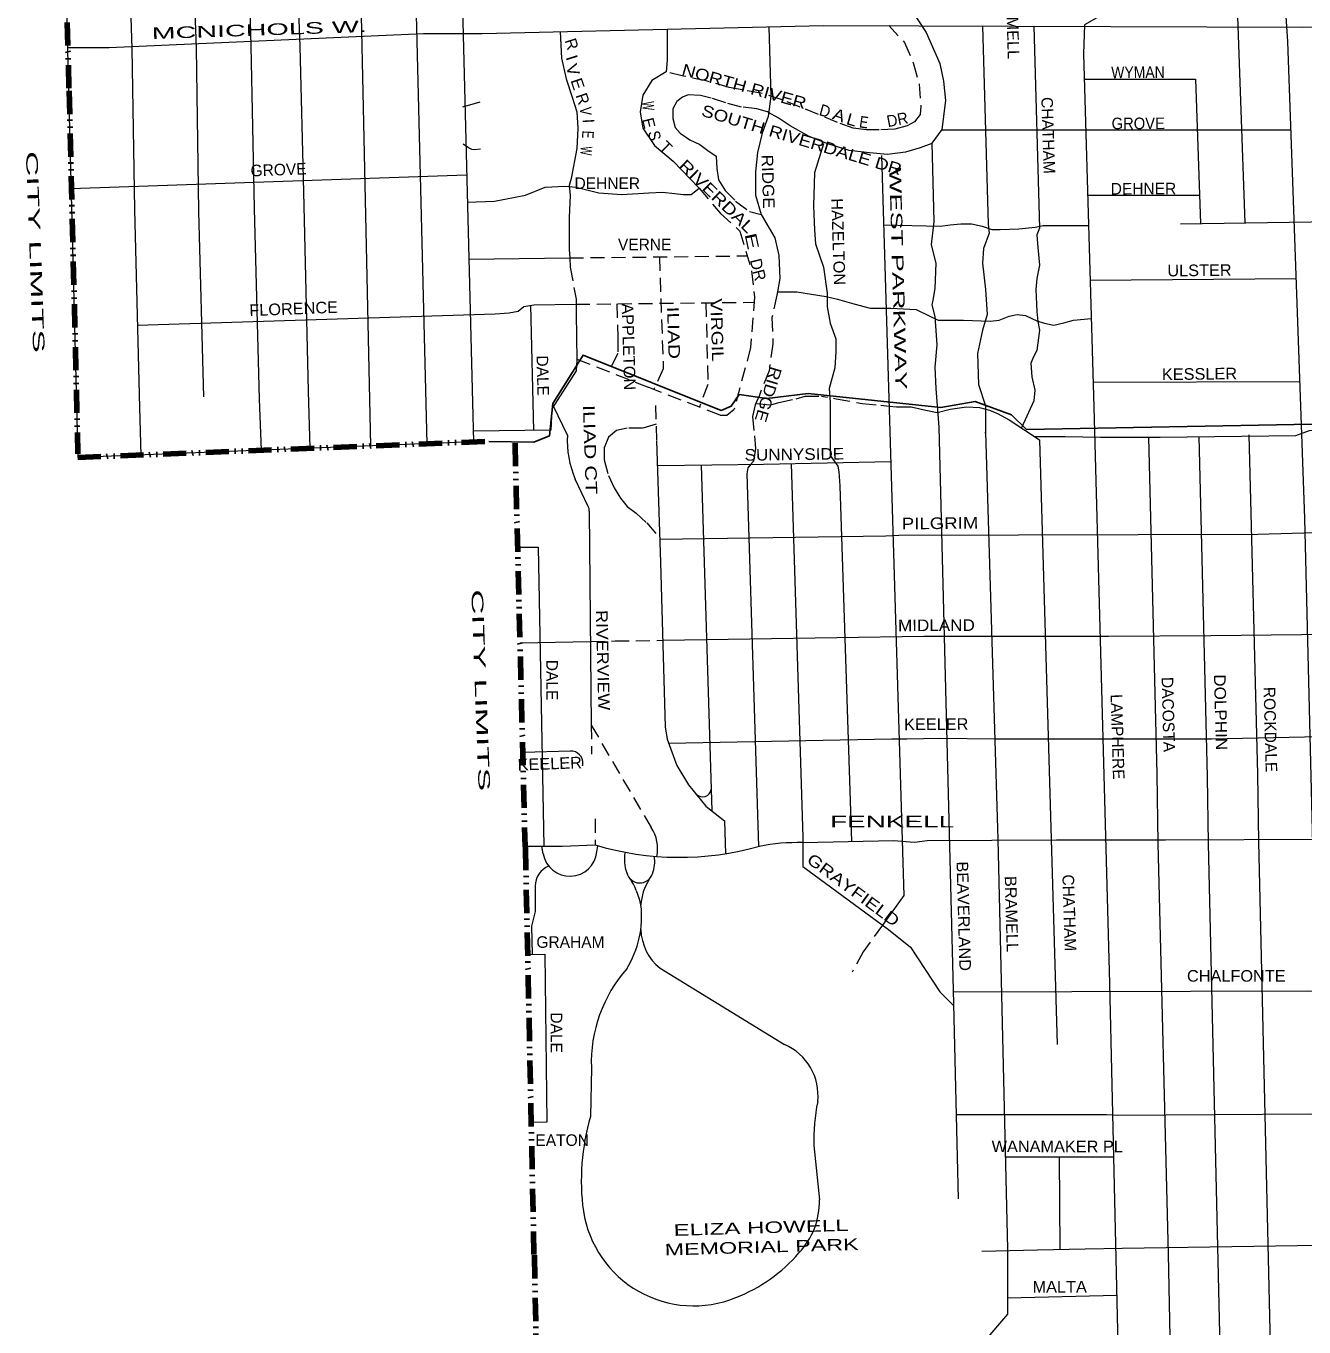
# Model space of a CAD drawing. Extents: x 34705 to 138605, y 34275 to 143551.
# Drawn here: x 34920 to 43181, y 121964 to 130370 of the extents above; entities that cross this region are included whole.
import ezdxf
from ezdxf.enums import TextEntityAlignment as Align

# ---------------------------------------------------------------- set-up
doc = ezdxf.new("R2010")
doc.units = 0
doc.header["$LTSCALE"] = 30
doc.linetypes.add('DASH_DOUBLE_DOT', pattern=[9.2, 5, -1.2, 0.3, -1.2, 0.3, -1.2])
doc.linetypes.add('MEDIUM_DASHED', pattern=[4.5, 3, -1.5])
for name, color, linetype, lineweight in [('1', 7, 'Continuous', 13), ('11', 7, 'Continuous', 13), ('59', 7, 'DASH_DOUBLE_DOT', 106)]:
    doc.layers.add(name, color=color, linetype=linetype, lineweight=lineweight)

msp = doc.modelspace()

# ---------------------------------------------------------------- linework, layer by layer
at = {"layer": '1'}
for p, q in [((34922.9, 140631.57), (35253.71, 127582.24)), ((41761.4, 130025.76), (42478.95, 130025.76)), ((42478.95, 130025.76), (42511.27, 129093.75)), ((37853.74, 129878.69), (37741.43, 129846.2)), ((40836.67, 129698.57), (43094.26, 129698.57)), ((35209.64, 129320.94), (37767.98, 129408.65)), ((41783.12, 129276.39), (42504.93, 129276.39)), ((42382.42, 129091.68), (46341.01, 129155.36)), ((37781.68, 128864.48), (38434.34, 128871.92)), ((41799.02, 128727.48), (43128.63, 128738.28)), ((38180.29, 128565.69), (38199.83, 127757.67)), ((41818.13, 128067.95), (43152.42, 128073.24)), ((38419.62, 127726.26), (38329.53, 127914.49)), ((37811.41, 127682.75), (35253.71, 127582.23)), ((38311.91, 127759.44), (37809.68, 127751.5)), ((39284.01, 127533.76), (39353.85, 125298.36)), ((38552.48, 127269.04), (38470.77, 127442.74)), ((38560.88, 127235.16), (38573.99, 125851.86)), ((38113.08, 126384.45), (38568.85, 126393.52)), ((38438.66, 125684.69), (38130.75, 125677.2)), ((38262.53, 125021.1), (38253.15, 125069.67)), ((38610.21, 125034.11), (38616.97, 125073.43)), ((38211.88, 124812.27), (38210.95, 124649.13)), ((38865.05, 124784.28), (38882.82, 124731.17)), ((38210.92, 124648.89), (38187.51, 124554.54)), ((38187.48, 124554.28), (38192.15, 124370.92)), ((39018.66, 124282.29), (39822.71, 123789.22)), ((38574.29, 123639.56), (38568.77, 123325.34)), ((40012.98, 123136.45), (40048.64, 122785.47)), ((41251.44, 123063.4), (41949.57, 123063.4)), ((41597.84, 123063.4), (41603.99, 122465.81)), ((41265.57, 122153.74), (41970.48, 122169.5))]:
    msp.add_line(p, q, dxfattribs=at)
at = {"layer": '1', "linetype": 'MEDIUM_DASHED'}
for p, q in [((38434.34, 128871.92), (39581.77, 128885.01)), ((38475.23, 128572.32), (39626.43, 128585.3)), ((38989.41, 127919.19), (38996.49, 127689.53)), ((38573.99, 125851.86), (38575.76, 125665.07)), ((38573.99, 125851.86), (38961.55, 125191.17)), ((38598.19, 125246.63), (38598.95, 125080.57))]:
    msp.add_line(p, q, dxfattribs=at)
at = {"layer": '1'}
for points in [[(42731.15, 140854.29), (42770.72, 138315.69), (42820.32, 138221.97), (42809.3, 138139.28), (42831.34, 137610.03), (42902.99, 132838.56), (43073.83, 130269.5), (43184.06, 127189.13), (43401.06, 118420.74)], [(37454.38, 140703.77), (37375.53, 140338.99), (37375.53, 140279.38), (37330.84, 140078.2), (37271.25, 139541.72), (37293.59, 139079.75), (37397.87, 138438.96), (37479.81, 138044.05), (37546.85, 137492.67), (37591.54, 136419.71), (37811.41, 127682.75)], [(36490.17, 135510.11), (36506.88, 134551.8), (36569.73, 134518.26), (36600.45, 133540.44), (36620.6, 132875.53), (36611.44, 132752.81), (36580.31, 132659.39), (36618.77, 131119.41), (36629.75, 130705.44), (36679.19, 130524.11), (36690.18, 130237.91), (36713.98, 129298.25), (36743.28, 128010.12), (36754.84, 127642.86)], [(37189.87, 135540.54), (37218.37, 134190.17), (37347.71, 134120.16), (37377.91, 132902.64), (37365.37, 132789.74), (37315.21, 132695.65), (37302.67, 132589.02), (37359.1, 130699.45), (37440.61, 130530.1), (37511.01, 127671.07)], [(35564.96, 135465.63), (35570.87, 135082.21), (35461.47, 135140.95), (35486.2, 134138.09), (35575.93, 131095.66), (35603.39, 130225.61), (35619.87, 129182.93), (35652.83, 127905.78), (35662.29, 127598.32)], [(35878.83, 135480.1), (35892.71, 135038.36), (35885.38, 134798.41), (35898.2, 134147.25), (35987.92, 131106.65), (36019.05, 130229.27), (36033.7, 129171.94), (36066.59, 127974.42)], [(36198.03, 135494.82), (36230.63, 134724.12), (36245.49, 134715.44), (36280.9, 133431.06), (36348.65, 131115.81), (36372.45, 130242.1), (36394.43, 129190.25), (36427.39, 127958.9), (36439, 127628.88)], [(42985.69, 131594.9), (42798.27, 131148.83), (42699.07, 130972.41), (42610.89, 130862.15), (41762.17, 130377.01), (41756.66, 130189.57), (41822.79, 127907.19), (41923.37, 124183.18), (42021.75, 119977.21)], [(35186.55, 130231.58), (35458.2, 130231.58), (37489.31, 130321.29), (37869.15, 130321.29), (40074.35, 130374.07), (43172.44, 130363.51), (44385.83, 130374.07), (48329.33, 130516.55), (49305.31, 130558.77), (49933.11, 130564.05), (54929.09, 130685.43), (56976.03, 130759.31), (58131.38, 130785.7), (58991.3, 130812.08), (60184.9, 130901.8), (61393.02, 130975.68), (61503.8, 130980.96), (63404.33, 131007.34), (65002.84, 131017.9), (66400.87, 131039.01), (66997.01, 131039.01), (67635.36, 131075.95), (68722.14, 131123.45), (70126.76, 131153.79)], [(36995.41, 131165.19), (37014.23, 130713.57), (37033.04, 130625.75), (37083.2, 130537.94), (37146.23, 127656.72)], [(42622.5, 130876.66), (42699.07, 130729.84), (42732.14, 130696.76), (42743.16, 130674.71), (42798.45, 129098.37)], [(40644.8, 130472.07), (40738.86, 130327.81), (40826.64, 130127.09), (40851.73, 130014.18), (40864.27, 129888.73), (40839.18, 129700.56), (40776.48, 129612.74), (40789.02, 129107.82), (40770.21, 128957.28), (40801.56, 128838.1), (40795.29, 128675.02), (40782.75, 128599.75), (40776.48, 128568.39), (40795.29, 128493.12), (40807.83, 128311.22), (40795.29, 128166.95), (40801.56, 128028.96), (40820.37, 127778.06), (40914.43, 124141.62), (40945.78, 122793.04)], [(38373.37, 130333.36), (38381.18, 130161.59), (38412.53, 130029.87), (38450.15, 129910.69), (38481.51, 129816.61), (38487.78, 129709.97), (38481.51, 129578.25), (38443.88, 129383.81), (38431.34, 129339.9), (38437.61, 129277.18), (38431.34, 129132.91), (38431.34, 128925.92), (38434.34, 128871.92)], [(39064.65, 130349.9), (39064.65, 130149.05), (39058.38, 130073.78), (38964.33, 130017.33), (38907.89, 129923.24), (38889.08, 129816.61), (38907.89, 129709.97), (38983.14, 129597.07), (39102.28, 129496.71), (39270.64, 129321.81)], [(39722, 130365.64), (39735.59, 129916.97), (39716.78, 129785.24), (39679.16, 129678.61), (39647.8, 129553.16), (39635.26, 129427.71), (39635.26, 129277.18), (39672.89, 129151.73), (39760.67, 129001.19), (39785.75, 128888.28), (39792.02, 128737.74), (39777.18, 128653.66)], [(41102.11, 130370.57), (41140.17, 129089), (41146.44, 129032.55), (41108.81, 128932.19), (41102.54, 128838.1), (41121.35, 128668.75), (41133.89, 128505.66), (41102.54, 128405.3), (41071.19, 128254.76), (41077.46, 128054.05), (41121.35, 127916.05), (41121.35, 127740.42), (41121.35, 127746.69), (41202.87, 125113.85), (41265.57, 122466.87), (41265.57, 122046.61), (40958.32, 121689.08)], [(41434.11, 130369.44), (41472.5, 129063.91), (41453.69, 129020), (41459.96, 128938.46), (41472.5, 128825.56), (41453.69, 128737.74), (41447.42, 128668.75), (41453.69, 128524.48), (41459.96, 128461.76), (41472.5, 128405.3), (41453.69, 128273.58), (41434.88, 128235.95), (41416.06, 128192.04), (41422.33, 128104.23), (41441.15, 128016.41), (41434.88, 127947.41), (41354.12, 127773.43)], [(40776.5, 129612.09), (40699.51, 129582.47), (40604.55, 129556.08), (40488.48, 129540.25), (40372.42, 129550.81), (40240.53, 129566.64), (40103.36, 129608.86), (39982.03, 129656.35), (39860.69, 129724.96), (39781.55, 129777.73), (39720.41, 129810.66)], [(37745.82, 129608.16), (37785.59, 129580.82), (37800.49, 129574.39), (37816.64, 129572.72), (37857.44, 129577.53)], [(40074.19, 129609.62), (40017.76, 129421.44), (40011.49, 129208.18), (40017.76, 129051.37), (40024.03, 128963.55), (40074.19, 128813.01), (40099.27, 128643.66), (40099.27, 128555.84), (40118.09, 128449.21), (40155.71, 128348.85), (40155.71, 128267.31), (40149.44, 128160.68), (40111.82, 128028.96), (40118.09, 127934.87), (40118.09, 127596.16), (40168.25, 127527.16), (40174.52, 127489.52), (40180.79, 127398.58), (40256.07, 125101.73)], [(40450.42, 129534.35), (40594.64, 124751.6), (40456.13, 124560.28)], [(37772.42, 129232.41), (37948.29, 129239.45), (38148.76, 129276.39), (38275.37, 129329.16), (38401.99, 129334.44), (38475.85, 129329.16), (38623.56, 129292.22), (38771.28, 129281.66), (38945.37, 129292.22), (39035.06, 129297.5), (39114.19, 129286.94), (39166.95, 129281.66), (39219.7, 129281.66), (39270.27, 129321.52)], [(40463.92, 129086.5), (40831.4, 129075.85), (40894.7, 129086.4), (40963.29, 129091.68), (41031.87, 129091.68), (41100.45, 129075.85), (41163.76, 129054.74), (41216.52, 129054.74), (41337.85, 129060.02), (41443.37, 129070.57), (41496.12, 129081.13), (41788.78, 129081.13)], [(39777.18, 128653.66), (39902.89, 128653.66), (40092.81, 128622), (40166.67, 128606.17), (40272.18, 128574.5), (40377.7, 128548.12), (40509.58, 128548.12), (40673.13, 128537.56), (40762.81, 128495.34), (40815.57, 128468.96), (40979.11, 128468.96), (41153.21, 128463.68), (41211.24, 128468.96), (41274.55, 128495.34), (41327.3, 128505.9), (41380.06, 128500.62), (41459.19, 128463.68), (41511.95, 128447.85), (41564.7, 128437.29), (41628.01, 128453.13), (41691.32, 128468.96), (41806.21, 128479.4)], [(35639.14, 128436.32), (37953.56, 128511.18), (38043.25, 128516.45), (38101.28, 128527.01), (38138.21, 128558.67), (38201.51, 128569.23), (38475.23, 128572.32)], [(38475.23, 128572.32), (38475.23, 128511.94), (38481.51, 128210.86), (38475.23, 128141.86), (38318.47, 127897.23), (38311.91, 127759.44)], [(40499.26, 127914.54), (40546.51, 127909.56), (40641.47, 127909.56), (40736.44, 127888.45), (40810.29, 127872.62), (40894.7, 127893.73), (41000.22, 127909.56), (41084.63, 127904.29), (41147.93, 127888.45), (41200.69, 127867.34), (41274.55, 127825.13), (41472.13, 127696.75)], [(41439.59, 127717.9), (41636.79, 127718.72), (41865.41, 127714.3), (42250.53, 127714.3), (43127.6, 127724.86), (43217.28, 127756.52), (48761.16, 127885.97)], [(38996.49, 127689.53), (39020.76, 126903.06), (39052.11, 125843.01), (39064.65, 125761.47), (39127.36, 125592.11), (39202.6, 125466.66), (39315.47, 125328.67), (39434.61, 125234.58), (39441.69, 125022.08)], [(41472.13, 127696.75), (41472.5, 127696.52), (41585.37, 123790.36)], [(42175.91, 127713.4), (42230.62, 125535.23), (42236.13, 125088.68), (42303.65, 122435.56), (42353.02, 119975.33)], [(42500.56, 127717.31), (42555.78, 125518.7), (42561.29, 125088.68), (42680.27, 119968.71)], [(42825.83, 127729.41), (42880.94, 125535.23), (42886.45, 125099.71), (42981.52, 121013.21)], [(39001.43, 127529.61), (39354.23, 127534.87), (39686.59, 127540.15), (40510.06, 127556.52)], [(39605.88, 127538.87), (39585.1, 127514.61), (39578.83, 127476.98), (39654.75, 125068.94)], [(39866.65, 127543.73), (39942.51, 125127.95), (39942.51, 125008.77), (39942.51, 124939.78), (40494.31, 124532.07), (40638.53, 124419.16), (40826.64, 124130.63), (40917.05, 124040.19)], [(39016.09, 127054.55), (40477.93, 127075.75), (40562.34, 127081.02), (42883.6, 127086.3), (44889.65, 127144.35), (45000.43, 127144.35), (46145.24, 127165.46), (49096.07, 127229.34)], [(38097.6, 127003.42), (38230.69, 127003.42), (38267.86, 125070.07)], [(39035.59, 126401.44), (40724.71, 126427.53), (41115.04, 126427.53), (41916.92, 126427.53), (42580.01, 126431.39), (43166, 126439.1), (44149.07, 126462.24), (50761.79, 126624.85)], [(39073.76, 125736.85), (40516.53, 125764.23), (40612.91, 125764.23), (40829.76, 125768.08), (41180.58, 125764.23), (41862.94, 125764.23), (42583.86, 125764.23), (43285.51, 125779.65), (44496.99, 125814.36), (45807.75, 125852.92), (46189.42, 125856.78), (48457.74, 125899.57)], [(39941.51, 125093.75), (40528.09, 125108.63), (40663.03, 125097.06), (40744.94, 125108.63), (41581.52, 125112.49), (42287.01, 125112.49), (43300.93, 125116.35), (44878.65, 125170.34), (48156.52, 125239.75), (49710.15, 125274.46), (51827.61, 125340.02), (53217.9, 125389.91), (53477.78, 125395.11), (53786.04, 125409.43)], [(38145.93, 125070.07), (38384.61, 125070.07), (38598.99, 125079.53)], [(40914.75, 124129.1), (43212.26, 124136.81), (43354.9, 124132.95), (44281.1, 124159.95), (49507.13, 124287.78), (49653.37, 124366.55), (49872.73, 124366.55), (53583.68, 124493.23)], [(38158.66, 124370.57), (38274.58, 124373.7), (38287.12, 123288.56), (38185.49, 123285.57)], [(40933.12, 123337.57), (41905.35, 123337.57), (41978.6, 123333.72), (43223.82, 123341.43), (43362.61, 123337.57), (44543.25, 123376.14), (44998.16, 123391.56), (45869.44, 123418.56), (45965.82, 123414.7), (48528.39, 123465.41)], [(41099.62, 122454.45), (41458.15, 122462.16), (41766.57, 122469.88), (42005.59, 122473.73), (43281.65, 122493.01), (43412.73, 122485.3), (47717.02, 122597.14), (53834.22, 122766.82), (57551.33, 122855.98)]]:
    msp.add_lwpolyline(points, dxfattribs=at)
at = {"layer": '1', "linetype": 'MEDIUM_DASHED'}
for points in [[(40497.21, 130372.63), (40599.27, 130263.24), (40657.3, 130126.03), (40694.23, 129994.1), (40704.78, 129851.61), (40699.51, 129798.84), (40662.58, 129751.34), (40615.1, 129724.96), (40535.96, 129703.85), (40435.73, 129698.57), (40351.32, 129698.57), (40266.91, 129709.13), (40166.67, 129746.07), (39923.99, 129846.34), (39807.93, 129893.83), (39670.76, 129936.05), (39549.43, 129957.16), (39465.02, 129972.99), (39317.3, 130015.21), (39169.58, 130046.87), (39058.38, 130073.78)], [(39720.41, 129810.66), (39712.97, 129814.67), (39644.39, 129835.78), (39544.15, 129846.34), (39443.91, 129872.72), (39348.95, 129904.39), (39280.37, 129920.22), (39201.24, 129925.5), (39164.31, 129909.66), (39127.38, 129883.28), (39101, 129835.78), (39101, 129772.45), (39116.83, 129714.4), (39148.48, 129677.46), (39211.79, 129635.24), (39275.09, 129603.58), (39327.85, 129566.64), (39380.61, 129529.7), (39385.88, 129450.54), (39396.43, 129376.65), (39438.64, 129308.05), (39507.22, 129239.44), (39596.91, 129170.84), (39672.81, 129151.86)], [(39270.27, 129321.52), (39409.53, 129158), (39534.94, 129045.09), (39610.18, 128787.92), (39628.99, 128618.57), (39603.91, 128292.4), (39497.65, 127895.57)], [(38434.34, 128871.92), (38437.61, 128813.01), (38475.23, 128606.02), (38475.23, 128572.32)], [(39013.94, 128878.53), (39039.57, 128154.4), (38977.28, 128022.86)], [(39777.18, 128653.66), (39773.21, 128631.11), (39741.86, 128486.85), (39748.13, 128317.49), (39723.05, 128141.86), (39660.35, 127985.05), (39633.65, 127922.81), (39616.45, 127847.05), (39628.99, 127721.61), (39635.26, 127640.06), (39622.72, 127558.52), (39605.88, 127538.87)], [(38738.38, 128575.29), (38744.86, 128355.12), (38744.86, 128254.76), (38686.25, 128137.49)], [(39315.3, 128581.79), (39328.01, 128054.05), (39272.66, 127908.7)], [(38481.35, 128218.4), (38942.73, 128036.22), (39406.98, 127856.79), (39449.19, 127856.79), (39497.65, 127895.57)], [(39639.14, 127932.01), (39735.68, 127922.81), (39786.69, 127936.73), (39897.62, 127962.34), (39955.65, 127978.17), (40061.16, 127978.17), (40100.32, 127971.64)], [(40139.38, 127965.13), (40156.12, 127962.34), (40324.94, 127930.67), (40446.28, 127920.12), (40499.26, 127914.54)], [(38993.17, 127797.32), (38905.8, 127772.35), (38805.57, 127772.35), (38736.98, 127756.52), (38684.23, 127714.3), (38657.85, 127645.7), (38657.85, 127566.54), (38684.23, 127466.27), (38721.16, 127387.11), (38763.36, 127318.5), (38805.57, 127265.73), (38863.6, 127223.51), (38932.18, 127160.18), (39015.87, 127061.52)], [(38568.85, 126393.52), (38727.73, 126396.68), (39035.59, 126401.44)], [(40456.13, 124560.28), (40331.28, 124387.8), (40260.4, 124256.17)]]:
    msp.add_lwpolyline(points, dxfattribs=at)
at = {"layer": '1', "lineweight": 25}
msp.add_lwpolyline([(37911.41, 127686.12), (38203.24, 127680.58), (38303.04, 127721.95), (38325.81, 127931.49), (38521.05, 128243.98), (39412.67, 127885.92), (39479.2, 127912.86), (39529.81, 127990.08), (39707.77, 127962.88), (39975.21, 127996.38), (40834.68, 127905.45), (41055.96, 127944.51), (41290.17, 127858.28), (41387.87, 127762.23), (48773.97, 127901.51)], dxfattribs=at)
at = {"layer": '1'}
for centre, radius, start, end in [((39033, 127690.56), 614.42, 176.66935, 203.78642), ((38510.54, 127240.66), 50.63, 353.76439, 34.09313), ((38443.02, 125608.16), 76.66, 43.69087, 93.26007), ((39293.14, 125447.17), 57.26, 224.34198, 350.14515), ((38762.66, 125056.32), 240.29, 347.60729, 34.13847), ((39146.1, 126895.46), 1896.56, 253.23335, 285.75016), ((39910.76, 123779.37), 1314.74, 88.65959, 101.07292), ((38435.54, 125052), 175.58, 189.99921, 354.15384), ((39042.87, 124986.91), 254.99, 169.7126, 200.16834), ((38781.3, 124970.3), 203.33, 337.75481, 9.84394), ((38346.03, 124815.82), 134.19, 110.89611, 181.51783), ((38887.31, 124919.67), 86.31, 193.8638, 342.22316), ((38645.97, 124729.85), 220.69, 29.15279, 38.63534), ((38706.01, 124738.44), 165.51, 16.07827, 36.70265), ((39214.27, 124678.5), 319.38, 146.49402, 177.70857), ((38252.97, 124618.26), 646.3, 328.32716, 6.48591), ((38724.07, 124660.29), 173.85, 10.26399, 24.06033), ((38209.95, 124649.13), 1, 346.06698, 359.67256), ((38188.48, 124554.3), 1, 166.06698, 181.45729), ((39226.07, 124541.32), 331.83, 181.58545, 231.31593), ((39496.32, 123670.29), 922.54, 138.72171, 181.90879), ((39683.65, 123461.21), 356.26, 353.4065, 67.0248), ((41218.62, 123175.07), 1206.26, 168.26958, 181.83431), ((39994.08, 122909.89), 1484.63, 163.74961, 187.65769), ((39570.43, 122774.1), 478.35, 316.3607, 1.36264), ((39235.84, 122822.95), 721.72, 188.83911, 292.11571), ((39139.66, 123108.17), 1022.15, 291.09202, 319.47412)]:
    msp.add_arc(centre, radius, start, end, dxfattribs=at)
at = {"layer": '1', "linetype": 'MEDIUM_DASHED'}
msp.add_arc((38443.02, 125608.16), 76.66, 346.35543, 43.69136, dxfattribs=at)
at = {"layer": '59'}
for p, q in [((35198.5, 129951.49), (35255.46, 127605.67)), ((35253.71, 127582.24), (37903.63, 127686.52)), ((38080.81, 127675.25), (38145.99, 125067.44)), ((38148.2, 125065.12), (38203.39, 122431.77)), ((38205.78, 122428.72), (38232.86, 121106.59))]:
    msp.add_line(p, q, dxfattribs=at)
msp.add_lwpolyline([(34926.08, 140631.66), (34977.99, 138118.71), (35197.94, 129943.33)], dxfattribs=at)

# ---------------------------------------------------------------- texts
at = {"layer": '1', "width": 2.25}
for p in [(34942.21, 128909.07), (37821.95, 126077.21)]:
    msp.add_text('CITY LIMITS', height=75, rotation=272.106, dxfattribs=at).set_placement(p, align=Align.CENTER)
at = {"layer": '11'}
for s, rotation, width, p in [('BRAMELL', 271.52, 1.05, (41259.96, 130401.08)), ('MCNICHOLS W.', 1.91, 1.85, (36428.75, 130308.39)), ('I', 287.519, 1.15, (38412.64, 130154)), ('V', 287.519, 1.1, (38418.61, 130076.15)), ('NORTH RIVER', 344.384, 1.2, (39552.68, 129944.21)), ('WYMAN', 0.421, 0.9, (42108.32, 130033.96)), ('E', 288.435, 1.1, (38450.48, 129984.25)), ('W', 272.201, 0.6, (38905.2, 129853.09)), ('V', 273.365, 0.8, (38500.21, 129818.39)), ('SOUTH RIVERDALE DR', 343.311, 1.2, (39923.69, 129598.64)), ('D', 344.384, 0.95, (40074.78, 129785.82)), ('A', 340.807, 1.15, (40163.54, 129758.26)), ('L', 344.384, 1.15, (40247.94, 129728.34)), ('E', 351.513, 0.85, (40330.79, 129711.68)), ('DR', 10.957, 0.95, (40559.58, 129729.17)), ('GROVE', 0.157, 0.95, (42109.84, 129703.49)), ('E', 267.275, 0.75, (38514.99, 129670.19)), ('S', 282.183, 0.95, (38946.33, 129653.87)), ('W', 267.275, 0.6, (38504.26, 129565.17)), ('RIDGE', 271.84, 1.1, (39679.44, 129363.28)), ('RIVERDAL', 315.883, 1.25, (39359.24, 129243.04)), ('WEST PARKWAY', 271.627, 1.75, (40520.54, 128736.55)), ('HAZELTON', 271.841, 1.05, (40133.77, 128975.47)), ('E ', 282.183, 1.6, (39580.4, 128950.25)), ('ULSTER', 0.563, 1.05, (42506.04, 128754.17)), ('VIRGIL', 271.704, 1.25, (39349.65, 128403.78)), ('FLORENCE', 2.198, 1.05, (36651.27, 128506.5)), ('APPLETON', 271.768, 1.05, (38778.09, 128296.46)), ('ILIAD', 271.653, 1.35, (39068.7, 128386.75)), ('RIDGE', 253.231, 1.15, (39682.62, 128000.28)), ('KESSLER', 0.622, 1.05, (42506.09, 128085.09)), ('ILIAD CT', 271.839, 1.4, (38529.18, 127631.79)), ('SUNNYSIDE', 0.749, 1.1, (39887.07, 127565.55)), ('PILGRIM', 0.655, 1.2, (40829.05, 127120.27)), ('RIVERVIEW', 271.387, 1.15, (38611.44, 126271.77)), ('MIDLAND', 0.236, 1.1, (40805.42, 126460.84)), ('DOLPHIN', 271.545, 1.1, (42605.54, 125935.31)), ('KEELER', 0.407, 1.05, (40804.24, 125821.83)), ('KEELER', 2.198, 1.05, (38306.68, 125566.98)), ('FENKELL', 359.96, 1.8, (40518.24, 125192.19)), ('GRAYFIELD', 323.405, 1.25, (40245.73, 124758.08)), ('BEAVERLAND', 271.578, 1.05, (40944.55, 124617.6)), ('BRAMELL', 271.517, 1.05, (41253.36, 124631.9)), ('WANAMAKER PL', 359.96, 1.05, (41586.16, 123093.87)), ('ELIZA HOWELL', 1.665, 1.55, (39672.6, 122569.28)), ('MEMORIAL PARK', 1.665, 1.5, (39676.24, 122444.33))]:
    msp.add_text(s, height=75, rotation=rotation, dxfattribs=dict(at, width=width)).set_placement(p, align=Align.CENTER)
for s, rotation, p in [('R', 287.519, (38411.37, 130241.96)), ('R', 288.435, (38482.66, 129887.45)), ('CHATHAM', 271.865, (41490.35, 129662.19)), ('I', 273.365, (38518.51, 129753.97)), ('E', 283.867, (38909.13, 129733.81)), ('T', 315.883, (39029.98, 129560.1)), ('GROVE', 2.184, (36553.65, 129404.77)), ('DEHNER', 0.222, (42143.76, 129281.93)), ('DR', 283.868, (39615.96, 128786.41)), ('DALE', 271.519, (38223.06, 128110)), ('DALE', 270, (38282.78, 126144.29)), ('DACOSTA', 271.545, (42266.99, 125920.98)), ('ROCKDALE', 271.435, (42926.82, 125823.54)), ('LAMPHERE', 271.635, (41938.98, 125776.2)), ('CHATHAM', 271.865, (41627.26, 124639.25)), ('DALE', 270, (38311.64, 123866.27))]:
    msp.add_text(s, height=75, rotation=rotation, dxfattribs=at).set_placement(p, align=Align.CENTER)
for s, p in [('DEHNER', (38677.39, 129316.5)), ('VERNE', (38919.06, 128921.26)), ('GRAHAM', (38439.14, 124414.07)), ('EATON', (38385.62, 123134.21))]:
    msp.add_text(s, height=75, dxfattribs=at).set_placement(p, align=Align.CENTER)
at = {"layer": '11', "width": 1.05}
for s, p in [('CHALFONTE', (42743.72, 124195.48)), ('MALTA', (41602.03, 122186.89))]:
    msp.add_text(s, height=75, dxfattribs=at).set_placement(p, align=Align.CENTER)

doc.saveas('drawing.dxf')
